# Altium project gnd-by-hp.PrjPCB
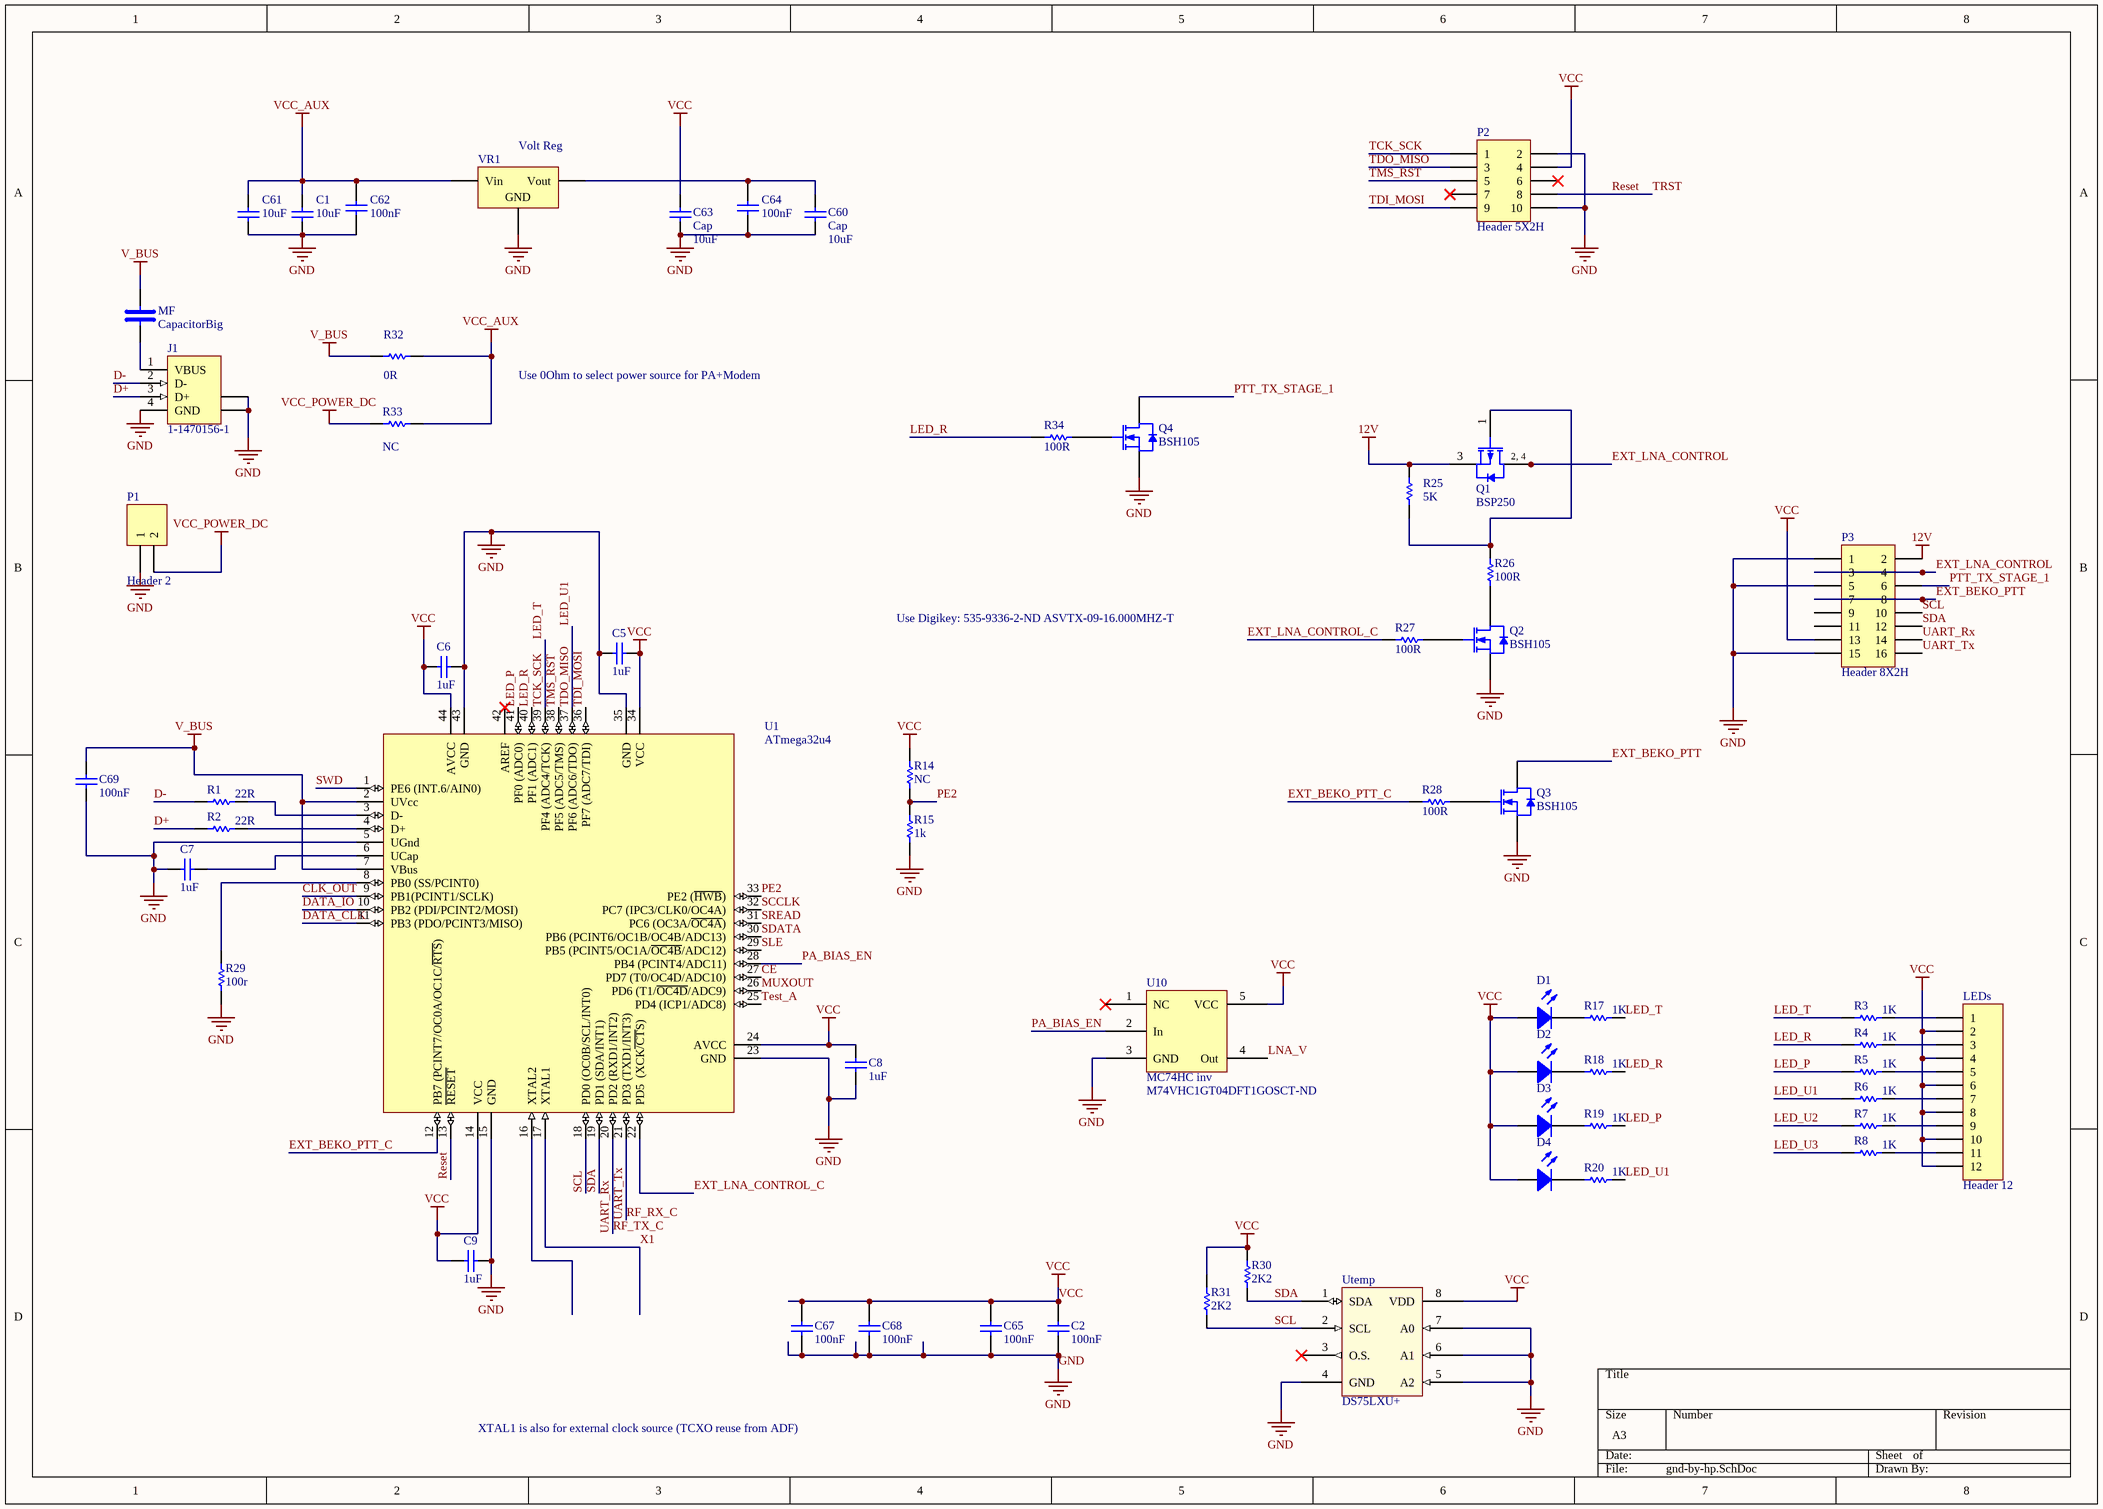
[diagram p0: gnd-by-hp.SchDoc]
4 sheets, 162 parts. Net scope: global (net labels, ports and power ports of the same name join across sheets).
Board files: gnd-by-hp.PcbDoc, aausat3_template.PCBDOC
Sheets:
  gnd-by-hp.SchDoc
  radio.SchDoc
  pa.SchDoc
  power.SchDoc

## Sheet gnd-by-hp.SchDoc
size A3; PageSetup: Record=PageOptions|CenterHorizontal=True|CenterVertical=True|PrintScale=0.71|XCorrection=1.00|YCorrection=1.00|PrintKind=0|BorderSize=5000000|LeftOffset=0|BottomOffset=0|Orientation=2|PaperLength=1000|PaperWidth=1000|Scale=100|PaperSource=7|PrintQuality=-4|MediaType=1|DitherType=10|PaperKind=A4|PrintScaleMode=1

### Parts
C1  value 10uF  [RAD-0.3]  (hidden comment: Cap)
C2  value 100nF  [C06]  (hidden comment: Capacitor)
C5  value 1uF  [CAPC3216L]  (hidden comment: Cap Semi)
C6  value 1uF  [CAPC3216L]  (hidden comment: Cap Semi)
C7  value 1uF  [CAPC3216L]  (hidden comment: Cap Semi)
C8  value 1uF  [CAPC3216L]  (hidden comment: Cap Semi)
C9  value 1uF  [CAPC3216L]  (hidden comment: Cap Semi)
C60  Cap  value 10uF  [RAD-0.3]
C61  value 10uF  [RAD-0.3]  (hidden comment: Cap)
C62  value 100nF  [C06]  (hidden comment: Capacitor)
C63  Cap  value 10uF  [RAD-0.3]
C64  value 100nF  [C06]  (hidden comment: Capacitor)
C65  value 100nF  [C06]  (hidden comment: Capacitor)
C67  value 100nF  [C06]  (hidden comment: Capacitor)
C68  value 100nF  [C06]  (hidden comment: Capacitor)
C69  value 100nF  [CAPC3216L]  (hidden comment: Cap Semi)
D1  LED  [L06]  (value not drawn)
D2  LED  [L06]  (value not drawn)
D3  LED  [L06]  (value not drawn)
D4  LED  [L06]  (value not drawn)
J1  1-1470156-1  [1-1470156]
LEDs  Header 12  [HDR1X12]
MF  CapacitorBig  [C1210]
P1  Header 2  [HDR1X2]
P2  Header 5X2H  [HDR2X5H]
P3  Header 8X2H  [HDR2X8H]
Q1  BSP250  [SOT223_N]
Q2  BSH105  [SOT23_N]
Q3  BSH105  [SOT23_N]
Q4  BSH105  [SOT23_N]
R1  value 22R  [AXIAL-0.5]  (hidden comment: Res Semi)
R2  value 22R  [AXIAL-0.5]  (hidden comment: Res Semi)
R3  value 1K  [AXIAL-0.5]  (hidden comment: Res Semi)
R4  value 1K  [AXIAL-0.5]  (hidden comment: Res Semi)
R5  value 1K  [AXIAL-0.5]  (hidden comment: Res Semi)
R6  value 1K  [AXIAL-0.5]  (hidden comment: Res Semi)
R7  value 1K  [AXIAL-0.5]  (hidden comment: Res Semi)
R8  value 1K  [AXIAL-0.5]  (hidden comment: Res Semi)
R14  value NC  [AXIAL-0.5]  (hidden comment: Res Semi)
R15  value 1k  [AXIAL-0.5]  (hidden comment: Res Semi)
R17  value 1K  [AXIAL-0.5]  (hidden comment: Res Semi)
R18  value 1K  [AXIAL-0.5]  (hidden comment: Res Semi)
R19  value 1K  [AXIAL-0.5]  (hidden comment: Res Semi)
R20  value 1K  [AXIAL-0.5]  (hidden comment: Res Semi)
R25  value 5K  [R06]  (hidden comment: Res Semi)
R26  value 100R  [R06]  (hidden comment: Res Semi)
R27  value 100R  [R06]  (hidden comment: Res Semi)
R28  value 100R  [R06]  (hidden comment: Res Semi)
R29  value 100r  [AXIAL-0.5]  (hidden comment: Res Semi)
R30  value 2K2  [AXIAL-0.5]  (hidden comment: Res Semi)
R31  value 2K2  [AXIAL-0.5]  (hidden comment: Res Semi)
R32  value 0R  [RESC1608L]  (hidden comment: Res Semi)
R33  value NC  [RESC1608L]  (hidden comment: Res Semi)
R34  value 100R  [R06]  (hidden comment: Res Semi)
U1  ATmega32u4  [44A_N]
U10  MC74HC inv  Supplier Part Number 1: M74VHC1GT04DFT1GOSCT-ND  [SOT353 for MC74HC]
Utemp  DS75LXU+  [uSOP8]
VR1  Volt Reg  [TO254P1510-3_4N]

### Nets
12V: P3.2 Q1.3(S) R25.2
GND: C1.1 C2.1 C5.1 C6.1 C7.2 C8.2 C9.1 C60.1 C61.1 C62.2 C63.1 C64.2 C65.1 C67.1 C68.1 C69.1 J1.4(GND) J1.5(SHLD) J1.6(SHLD) P1.1 P2.2 P2.10 P3.1 P3.5 P3.15 Q2.2(S) Q3.2(S) Q4.2(S) R15.1 R29.1 U1.5(UGnd) U1.15(GND) U1.23(GND) U1.35(GND) U1.43(GND) U10.3(GND) Utemp.4(GND) Utemp.5(A2) Utemp.6(A1) Utemp.7(A0) VR1.2(GND)
V_BUS: C69.2 MF.1 R32.1 U1.2(UVcc) U1.7(VBus)
VCC: C2.2 C5.2 C6.2 C8.1 C9.2 C63.2 C65.2 C67.2 C68.2 D1.1(A) D2.1(A) D3.1(A) D4.1(A) LEDs.2 LEDs.4 LEDs.6 LEDs.8 LEDs.10 LEDs.12 P2.4 P3.13 R14.2 R30.2 R31.2 U1.14(VCC) U1.24(AVCC) U1.34(VCC) U1.44(AVCC) U10.5(VCC) Utemp.8(VDD)
VCC_AUX: C1.2 C61.2 C62.1 R32.2 R33.2 VR1.1(Vin)
VCC_POWER_DC: P1.2 R33.1
CE: U1.27(PD7_(T0/OC4D/ADC10))
CLK_OUT: U1.9(PB1(PCINT1/SCLK))
D+: J1.3(D+) R2.1
D-: J1.2(D-) R1.1
DATA_CLK: U1.11(PB3_(PDO/PCINT3/MISO))
DATA_IO: U1.10(PB2_(PDI/PCINT2/MOSI))
EXT_BEKO_PTT: P3.7 P3.8 Q3.3(D)
EXT_BEKO_PTT_C: R28.2 U1.12(PB7_(PCINT7/OC0A/OC1C/~{RTS}))
EXT_LNA_CONTROL: P3.3 P3.4 Q1.2(D) Q1.4(D)
EXT_LNA_CONTROL_C: R27.2 U1.22(PD5__(XCK~{/CT}S))
LED_P: R5.1 R19.2 U1.41(PF0_(ADC0))
LED_R: R4.1 R18.2 R34.2 U1.40(PF1_(ADC1))
LED_T: P2.1 R3.1 R17.2 U1.39(PF4_(ADC4/TCK))  [also labelled TCK_SCK]
LED_U1: P2.3 R6.1 R20.2 U1.37(PF6_(ADC6/TDO))  [also labelled TDO_MISO]
LED_U2: R7.1
LED_U3: R8.1
LNA_V: U10.4(Out)
MUXOUT: U1.26(PD6_(T1/~{OC4D}/ADC9))
PA_BIAS_EN: U1.28(PB4_(PCINT4/ADC11)) U10.2(In)
PE2: R14.1 R15.2 U1.33(PE2_(~{HWB}))
PTT_TX_STAGE_1: P3.6 Q4.3(D)
Reset: P2.8 U1.13(~{RESET})  [also labelled TRST]
RF_RX_C: P3.16 U1.21(PD3_(TXD1/INT3))  [also labelled UART_Tx]
RF_TX_C: P3.14 U1.20(PD2_(RXD1/INT2))  [also labelled UART_Rx]
SCCLK: U1.32(PC7_(IPC3/CLK0/OC4A))
SCL: P3.10 R31.1 U1.18(PD0_(OC0B/SCL/INT0)) Utemp.2(SCL)
SDA: P3.12 R30.1 U1.19(PD1_(SDA/INT1)) Utemp.1(SDA)
SDATA: U1.30(PB6_(PCINT6/OC1B/OC4B/ADC13))
SLE: U1.29(PB5_(PCINT5/OC1A/~{OC4B}/ADC12))
SREAD: U1.31(PC6_(OC3A/~{OC4A}))
SWD: U1.1(PE6_(INT.6/AIN0))
TDI_MOSI: P2.9 U1.36(PF7_(ADC7/TDI))
Test_A: U1.25(PD4_(ICP1/ADC8))
TMS_RST: P2.5 U1.38(PF5_(ADC5/TMS))
X1: U1.17(XTAL1)
NetC7_1: C7.1 U1.6(UCap)
NetC60_2: C60.2 C64.1 VR1.3(Vout)
NetD1_2: D1.2(K) R17.1
NetD2_2: D2.2(K) R18.1
NetD3_2: D3.2(K) R19.1
NetD4_2: D4.2(K) R20.1
NetJ1_1: J1.1(VBUS) MF.2
NetLEDs_1: LEDs.1 R3.2
NetLEDs_3: LEDs.3 R4.2
NetLEDs_5: LEDs.5 R5.2
NetLEDs_7: LEDs.7 R6.2
NetLEDs_9: LEDs.9 R7.2
NetLEDs_11: LEDs.11 R8.2
NetQ1_1: Q1.1(G) R25.1 R26.1
NetQ2_1: Q2.1(G) R27.1
NetQ2_3: Q2.3(D) R26.2
NetQ3_1: Q3.1(G) R28.1
NetQ4_1: Q4.1(G) R34.1
NetR1_2: R1.2 U1.3(D-)
NetR2_2: R2.2 U1.4(D+)
NetR29_2: R29.2 U1.8(PB0_(SS/PCINT0))

Not connected (* = marked no-connect by the designer): P2 6* 7*; P3 9 11; U1 16(XTAL2) 42(AREF)*; U10 1(NC)*; Utemp 3(O.S.)*

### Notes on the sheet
- Use 0Ohm to select power source for PA+Modem
- Use Digikey: 535-9336-2-ND ASVTX-09-16.000MHZ-T
- XTAL1 is also for external clock source (TCXO reuse from ADF)

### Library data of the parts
C1 C60 C61 C63 = Cap: Capacitor
C2 C62 C64 C65 C67 C68 = Capacitor: Capacitor, standard
C5-C9 C69 = Cap Semi: Capacitor (Semiconductor SIM Model)
D1-D4 = LED: Typical RED GaAs LED
J1 = 1-1470156-1: USB 1.1, Right Angle, Thru-Hole, B Type, Receptacle, 4 Position, White; ContactMaterial: Phosphor Bronze; ContactPlating: Gold over Nickel; TerminationLength: 3.00mm [0.118in.]; PCB_Layout: Complies with manufacturer's recommendation.; DrillSize: Corresponds to nominal value.; PanelGround: Without
LEDs = Header 12: Header, 12-Pin
MF = CapacitorBig: Capacitor for PRU etc.; By: Troels Jessen; Username: tjessen
P1 = Header 2: Header, 2-Pin
P2 = Header 5X2H: Header, 5-Pin, Dual row, Right Angle
P3 = Header 8X2H: Header, 8-Pin, Dual row, Right Angle
Q1 = BSP250: P-channel Enhancement Mode Vertical D-MOSFET
Q2-Q4 = BSH105: N-channel Enhancement Mode MOSFET
R1-R8 R14 R15 R17-R20 R25-R34 = Res Semi: Semiconductor Resistor
U1 = ATmega32u4: 8-Bit AVR Microcontroller with 32K Bytes of In-System Programmable Flash Memory
Utemp = DS75LXU+: Digital Thermometer and Thermostat; By: hp000
VR1 = Volt Reg: Voltage Regulator

## Sheet radio.SchDoc
size A3
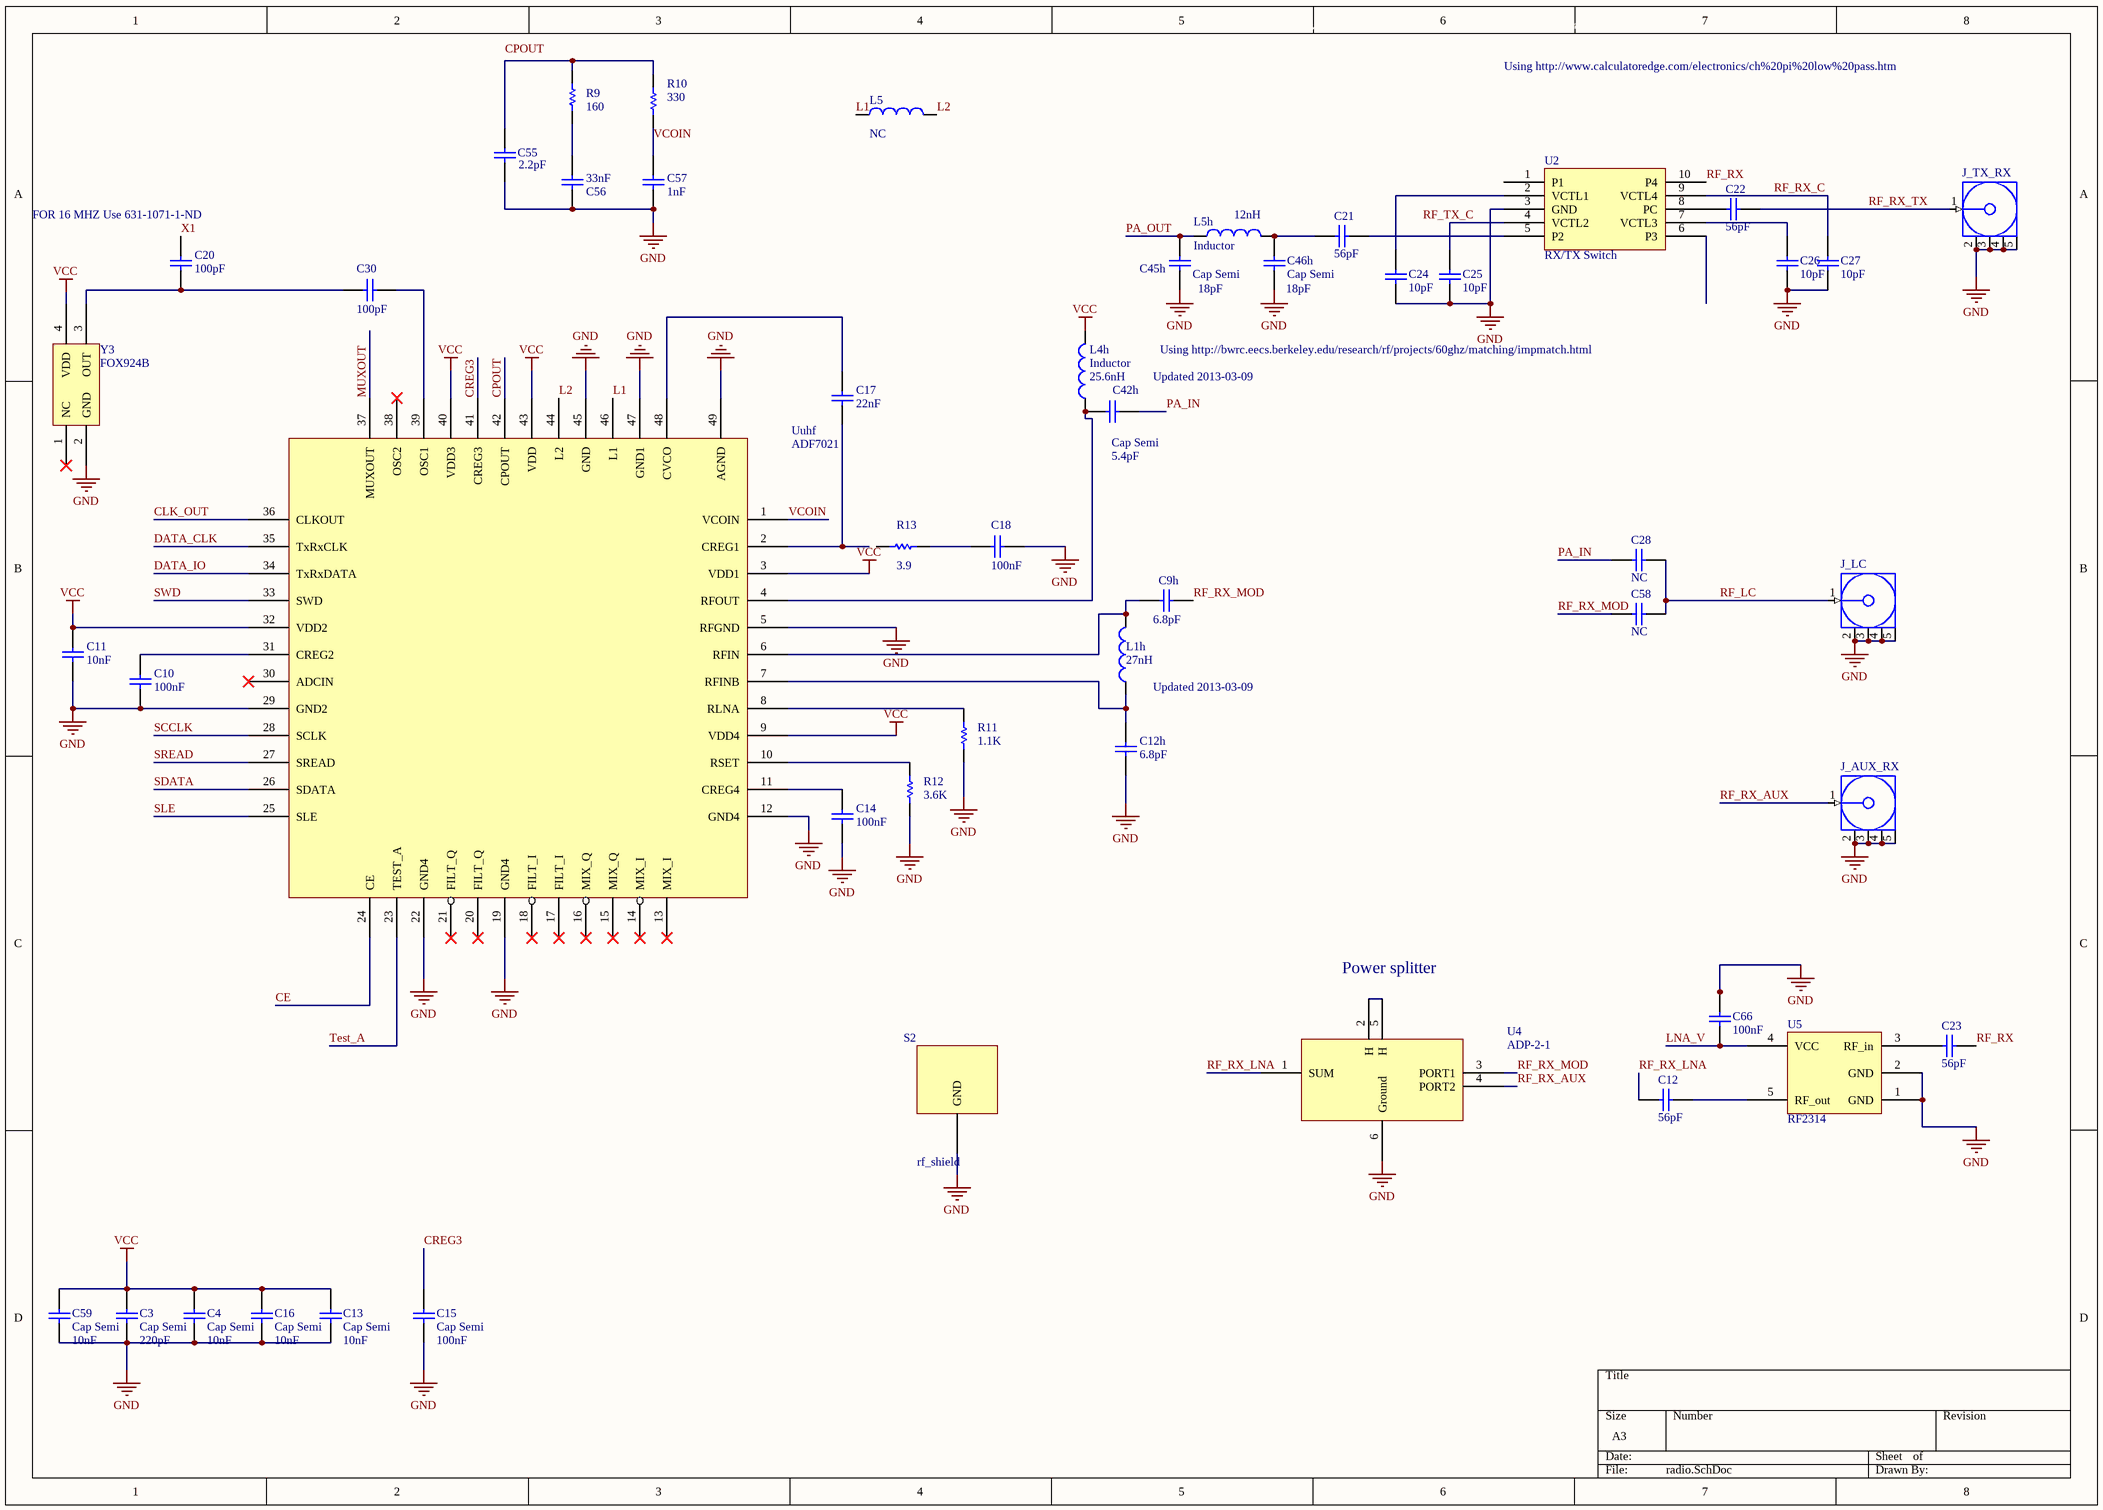
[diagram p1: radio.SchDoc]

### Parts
C3  Cap Semi  value 220pF  [C06]
C4  Cap Semi  value 10nF  [C06]
C9h  value 6.8pF  [C06]  (hidden comment: Cap Semi)
C10  value 100nF  [C06]  (hidden comment: Cap Semi)
C11  value 10nF  [C06]  (hidden comment: Cap Semi)
C12  value 56pF  [C06]  (hidden comment: Capacitor)
C12h  value 6.8pF  [C06]  (hidden comment: Cap Semi)
C13  Cap Semi  value 10nF  [C06]
C14  value 100nF  [C06]  (hidden comment: Cap Semi)
C15  Cap Semi  value 100nF  [C06]
C16  Cap Semi  value 10nF  [C06]
C17  value 22nF  [C06]  (hidden comment: Cap Semi)
C18  value 100nF  [C06]  (hidden comment: Cap Semi)
C20  value 100pF  [C06]  (hidden comment: Cap Semi)
C21  value 56pF  [C06]  (hidden comment: Capacitor)
C22  value 56pF  [C06]  (hidden comment: Capacitor)
C23  value 56pF  [C06]  (hidden comment: Capacitor)
C24  value 10pF  [C06]  (hidden comment: Capacitor)
C25  value 10pF  [C06]  (hidden comment: Capacitor)
C26  value 10pF  [C06]  (hidden comment: Capacitor)
C27  value 10pF  [C06]  (hidden comment: Capacitor)
C28  value NC  [C06]  (hidden comment: Capacitor)
C30  value 100pF  [C06]  (hidden comment: Cap Semi)
C42h  Cap Semi  value 5.4pF  [C06]
C45h  Cap Semi  value 18pF  [C06]
C46h  Cap Semi  value 18pF  [C06]
C55  value 2.2pF  [C06]  (hidden comment: Cap Semi)
C56  value 33nF  [C06]  (hidden comment: Cap Semi)
C57  value 1nF  [C06]  (hidden comment: Cap Semi)
C58  value NC  [C06]  (hidden comment: Capacitor)
C59  Cap Semi  value 10nF  [C06]
C66  value 100nF  [C06]  (hidden comment: Capacitor)
J_AUX_RX  COAX-F  [MCX5.08-H5]  (value not drawn)
J_LC  COAX-F  [MCX5.08-H5]  (value not drawn)
J_TX_RX  COAX-F  [MCX5.08-H5]  (value not drawn)
L1h  value 27nH  [B82464-G4]  (hidden comment: Inductor)
L4h  Inductor  value 25.6nH  [B82464-G4]
L5  value NC  [INDC1005AL]  (hidden comment: Inductor)
L5h  Inductor  value 12nH  [B82464-G4]
R9  value 160  [R06]  (hidden comment: Res Semi)
R10  value 330  [R06]  (hidden comment: Res Semi)
R11  value 1.1K  [R06]  (hidden comment: Res Semi)
R12  value 3.6K  [R06]  (hidden comment: Res Semi)
R13  value 3.9  [R06]  (hidden comment: Res Semi)
S2  rf_shield  [rf_can_shield]
U2  RX/TX Switch  [FLP10]
U4  ADP-2-1  [ADP-2-1]
U5  RF2314  [SOT95P280X144-5M]
Uuhf  ADF7021  [QFN50P700X700X100-48M]
Y3  FOX924B  [Fox924]

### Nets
GND: C3.1 C4.1 C10.1 C11.1 C12h.1 C13.1 C14.1 C15.1 C16.1 C18.2 C24.1 C25.1 C26.1 C27.1 C45h.1 C46h.1 C55.1 C56.1 C57.1 C59.1 C66.1 J_AUX_RX.2(GND) J_AUX_RX.3(GND) J_AUX_RX.4(GND) J_AUX_RX.5(GND) J_LC.2(GND) J_LC.3(GND) J_LC.4(GND) J_LC.5(GND) J_TX_RX.2(GND) J_TX_RX.3(GND) J_TX_RX.4(GND) J_TX_RX.5(GND) R11.2 R12.1 S2.0(GND) U2.3(GND) U4.6(Ground) U5.1(GND) U5.2(GND) Uuhf.5(RFGND) Uuhf.12(GND4) Uuhf.19(GND4) Uuhf.22(GND4) Uuhf.29(GND2) Uuhf.45(GND) Uuhf.47(GND1) Uuhf.49(AGND) Y3.2(GND)
VCC: C3.2 C4.2 C11.2 C13.2 C16.2 C59.2 L4h.2 Uuhf.3(VDD1) Uuhf.9(VDD4) Uuhf.32(VDD2) Uuhf.40(VDD3) Uuhf.43(VDD) Y3.4(VDD)
CE: Uuhf.24(CE)
CLK_OUT: Uuhf.36(CLKOUT)
CPOUT: Uuhf.42(CPOUT)
CREG3: C15.2 Uuhf.41(CREG3)
DATA_CLK: Uuhf.35(TxRxCLK)
DATA_IO: Uuhf.34(TxRxDATA)
L1: L5.1 Uuhf.46(L1)
L2: L5.2 Uuhf.44(L2)
LNA_V: C66.2 U5.4(VCC)
MUXOUT: Uuhf.37(MUXOUT)
PA_IN: C28.2 C42h.2
PA_OUT: C45h.2 L5h.1
RF_LC: C28.1 C58.1 J_LC.1(Signal)
RF_RX: C23.1 U2.10(P4)
RF_RX_AUX: J_AUX_RX.1(Signal) U4.4(PORT2)
RF_RX_C: C27.2 U2.9(VCTL4)
RF_RX_LNA: C12.2 U4.1(SUM)
RF_RX_MOD: C9h.1 C58.2 U4.3(PORT1)
RF_RX_TX: C22.1 J_TX_RX.1(Signal)
SCCLK: Uuhf.28(SCLK)
SDATA: Uuhf.26(SDATA)
SLE: Uuhf.25(SLE)
SREAD: Uuhf.27(SREAD)
SWD: Uuhf.33(SWD)
Test_A: Uuhf.23(TEST_A)
VCOIN: C57.2 R10.1 Uuhf.1(VCOIN)
X1: C20.2
NetC9h_2: C9h.2 L1h.2 Uuhf.6(RFIN)
NetC10_2: C10.2 Uuhf.31(CREG2)
NetC12_1: C12.1 U5.5(RF_out)
NetC12h_2: C12h.2 L1h.1 Uuhf.7(RFINB)
NetC14_2: C14.2 Uuhf.11(CREG4)
NetC17_1: C17.1 Uuhf.2(CREG1)
NetC17_2: C17.2 Uuhf.48(CVCO)
NetC18_1: C18.1 R13.2
NetC20_1: C20.1 C30.1 Y3.3(OUT)
NetC21_1: C21.1 U2.5(P2)
NetC21_2: C21.2 C46h.2 L5h.2
NetC22_2: C22.2 U2.8(PC)
NetC23_2: C23.2 U5.3(RF_in)
NetC24_2: C24.2 U2.2(VCTL1)
NetC25_2: C25.2 U2.4(VCTL2)
NetC26_2: C26.2 U2.7(VCTL3)
NetC30_2: C30.2 Uuhf.39(OSC1)
NetC42h_1: C42h.1 L4h.1 Uuhf.4(RFOUT)
NetC55_2: C55.2 R9.2 R10.2
NetC56_2: C56.2 R9.1
NetR11_1: R11.1 Uuhf.8(RLNA)
NetR12_2: R12.2 Uuhf.10(RSET)
NetU4_2: U4.2(H) U4.5(H)

Not connected (* = marked no-connect by the designer): R13 1; U2 1(P1) 6(P3); Uuhf 13(MIX_I)* 14(MIX_I)* 15(MIX_Q)* 16(MIX_Q)* 17(FILT_I)* 18(FILT_I)* 20(FILT_Q)* 21(FILT_Q)* 30(ADCIN)* 38(OSC2)*; Y3 1(NC)*

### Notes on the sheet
- Using http://www.calculatoredge.com/electronics/ch%20pi%20low%20pass.htm
- (near C20) FOR 16 MHZ Use 631-1071-1-ND
- Updated 2013-03-09
- Using http://bwrc.eecs.berkeley.edu/research/rf/projects/60ghz/matching/impmatch.html
- (near L1h) Updated 2013-03-09
- Power splitter
- Labels drawn without touching a wire or pin: CPOUT, RF_TX_C

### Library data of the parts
C3 C4 C9h C10 C11 C12h C13-C18 C20 C30 C42h C45h C46h C55-C57 C59 = Cap Semi: Capacitor (Semiconductor SIM Model)
C12 C21-C28 C58 C66 = Capacitor: Capacitor, standard
J_AUX_RX J_LC J_TX_RX = COAX-F: RF Coaxial PCB Connector, MCX; Thru-Hole, Right-Angle Mount Socket, Blunt Post Terminal, 50 Ohm Impedance; PCB_Layout: Complies with manufacturer's recommendation.; DrillSize: Corresponds to nominal value.
L5 = Inductor: Code_IEC: 1005
R9-R13 = Res Semi: Semiconductor Resistor
S2 = rf_shield: RF Shielding; Manufacturer: Fotofab; By: HP; Description: SHIELD RF STD 1 X 1 X .25"
U2 = NJG1519KC1-TE3: SP4T SWITCH GaAs MMIC, up to 2.5GHz.; By: Hans Peter Mortensen
U4 = ADP-2-1: 2 way power splitter; By: Hans Peter aau; Producent: Mini-Circuits
U5 = RF2314: LNA from RFMD no external components; By: Nikolaj B. Pedersen
Uuhf = ADF7021: ADF7021 transceiver; By: Nikolaj Bisgaard Pedersen
Y3 = FOX924B: FOX924B TCXO 19.44 MHz; By: Nikolaj B. Pedersen; Username: Markem

## Sheet pa.SchDoc
size A4
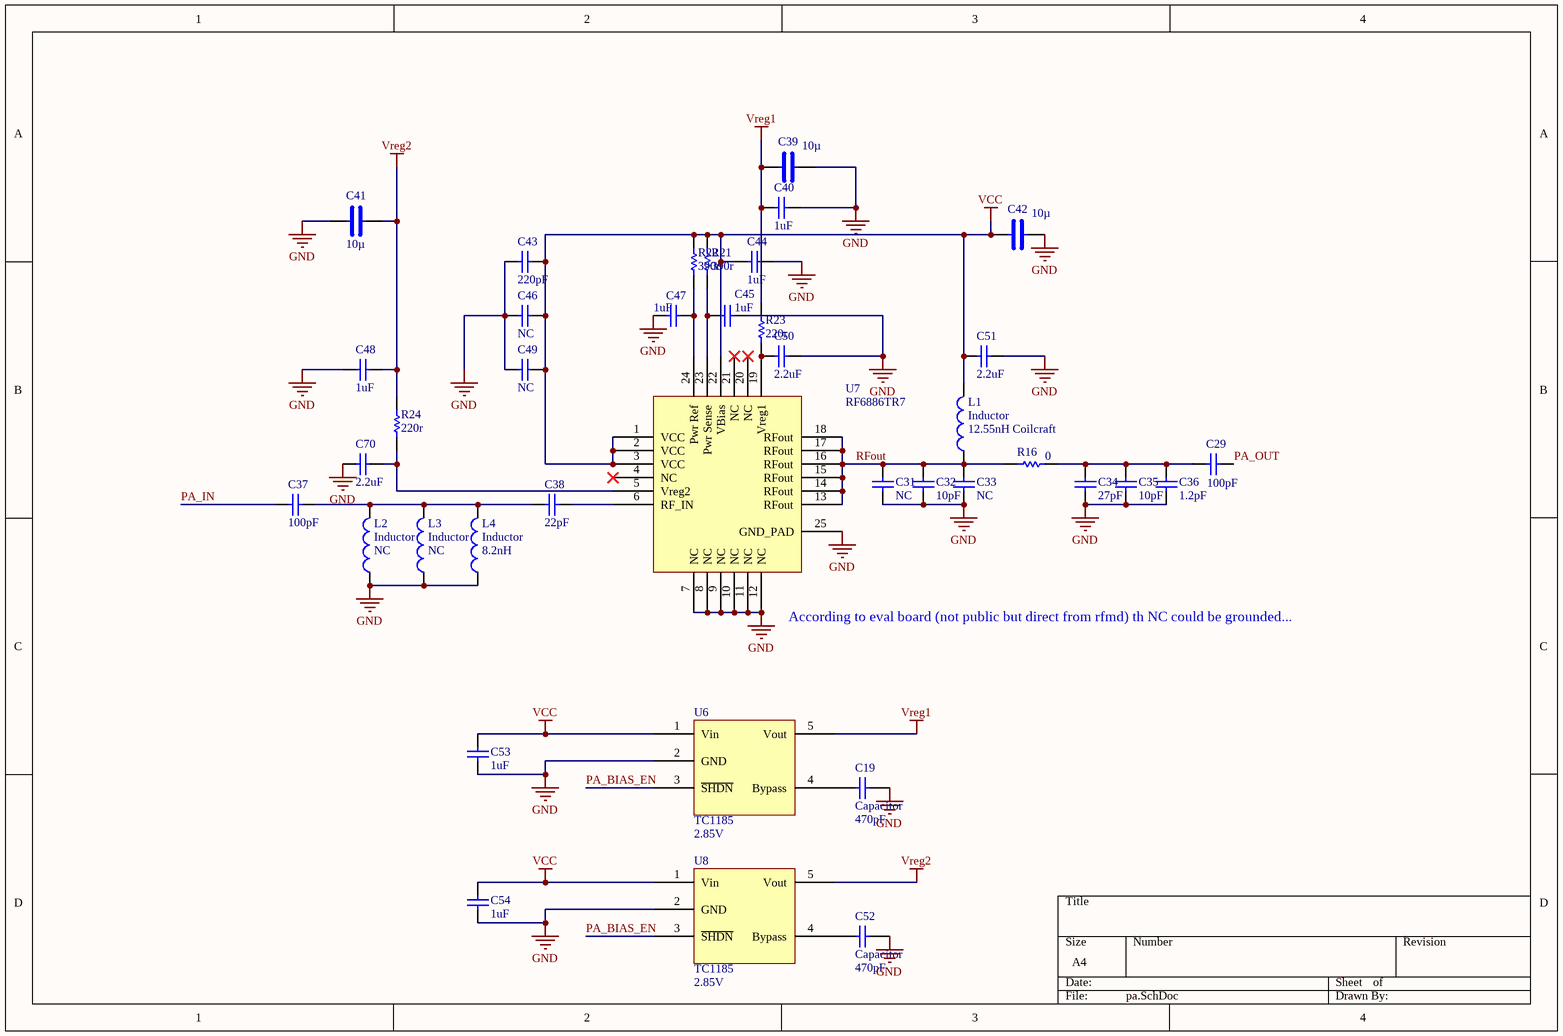
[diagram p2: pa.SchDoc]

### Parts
C19  Capacitor  value 470pF  [C06]
C29  value 100pF  [CAPC3216L]  (hidden comment: Cap Semi)
C31  value NC  [CAPC3216L]  (hidden comment: Cap Semi)
C32  value 10pF  [CAPC3216L]  (hidden comment: Cap Semi)
C33  value NC  [CAPC3216L]  (hidden comment: Cap Semi)
C34  value 27pF  [CAPC3216L]  (hidden comment: Cap Semi)
C35  value 10pF  [CAPC3216L]  (hidden comment: Cap Semi)
C36  value 1.2pF  [CAPC3216L]  (hidden comment: Cap Semi)
C37  value 100pF  [CAPC3216L]  (hidden comment: Cap Semi)
C38  value 22pF  [CAPC3216L]  (hidden comment: Cap Semi)
C39  value 10µ  [C1210]  (hidden comment: CapacitorBig)
C40  value 1uF  [CAPC3216L]  (hidden comment: Cap Semi)
C41  value 10µ  [C1210]  (hidden comment: CapacitorBig)
C42  value 10µ  [C1210]  (hidden comment: CapacitorBig)
C43  value 220pF  [CAPC3216L]  (hidden comment: Cap Semi)
C44  value 1uF  [CAPC3216L]  (hidden comment: Cap Semi)
C45  value 1uF  [CAPC3216L]  (hidden comment: Cap Semi)
C46  value NC  [CAPC3216L]  (hidden comment: Cap Semi)
C47  value 1uF  [CAPC3216L]  (hidden comment: Cap Semi)
C48  value 1uF  [CAPC3216L]  (hidden comment: Cap Semi)
C49  value NC  [CAPC3216L]  (hidden comment: Cap Semi)
C50  value 2.2uF  [CAPC3216L]  (hidden comment: Cap Semi)
C51  value 2.2uF  [CAPC3216L]  (hidden comment: Cap Semi)
C52  Capacitor  value 470pF  [C06]
C53  value 1uF  [CAPC3216L]  (hidden comment: Cap Semi)
C54  value 1uF  [CAPC3216L]  (hidden comment: Cap Semi)
C70  value 2.2uF  [CAPC3216L]  (hidden comment: Cap Semi)
L1  Inductor  value 12.55nH Coilcraft  [INDC1005AL]
L2  Inductor  value NC  [INDC1005AL]
L3  Inductor  value NC  [INDC1005AL]
L4  Inductor  value 8.2nH  [INDC1005AL]
R16  value 0  [AXIAL-0.5]  (hidden comment: Res Semi)
R21  value 390r  [AXIAL-0.5]  (hidden comment: Res Semi)
R22  value 390r  [AXIAL-0.5]  (hidden comment: Res Semi)
R23  value 220r  [AXIAL-0.5]  (hidden comment: Res Semi)
R24  value 220r  [AXIAL-0.5]  (hidden comment: Res Semi)
U6  TC1185  Voltage: 2.85V  [SOT23 - 5 for microchip]
U7  RF6886TR7  [QFN24-4-4]
U8  TC1185  Voltage: 2.85V  [SOT23 - 5 for microchip]

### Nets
GND: C19.1 C31.1 C32.1 C33.1 C34.1 C35.1 C36.1 C39.2 C40.1 C41.1 C42.2 C43.2 C44.2 C45.2 C46.2 C47.1 C48.2 C49.2 C50.1 C51.1 C52.1 C53.1 C54.1 C70.2 L2.1 L3.1 L4.1 U6.2(GND) U7.7(NC) U7.8(NC) U7.9(NC) U7.10(NC) U7.11(NC) U7.12(NC) U7.25(GND_PAD) U8.2(GND)
VCC: C42.1 C43.1 C44.1 C46.1 C49.1 C51.2 C53.2 C54.2 L1.2 R21.2 R22.2 U6.1(Vin) U7.1(VCC) U7.2(VCC) U7.3(VCC) U7.22(VBias) U8.1(Vin)
Vreg1: C39.1 C40.2 R23.1 U6.5(Vout)
Vreg2: C41.2 C48.1 R24.2 U8.5(Vout)
PA_BIAS_EN: U6.3(~{SHDN}) U8.3(~{SHDN})
PA_IN: C37.2
PA_OUT: C29.2
RFout: C31.2 C32.2 C33.2 L1.1 R16.1 U7.13(RFout) U7.14(RFout) U7.15(RFout) U7.16(RFout) U7.17(RFout) U7.18(RFout)
NetC19_2: C19.2 U6.4(Bypass)
NetC29_1: C29.1 C34.2 C35.2 C36.2 R16.2
NetC37_1: C37.1 C38.2 L2.2 L3.2 L4.2
NetC38_1: C38.1 U7.6(RF_IN)
NetC45_1: C45.1 R21.1 U7.23(Pwr_Sense)
NetC47_2: C47.2 R22.1 U7.24(Pwr_Ref)
NetC50_2: C50.2 R23.2 U7.19(Vreg1)
NetC52_2: C52.2 U8.4(Bypass)
NetC70_1: C70.1 R24.1 U7.5(Vreg2)

Not connected (* = marked no-connect by the designer): U7 4(NC)* 20(NC)* 21(NC)*

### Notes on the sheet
- (near U7) According to eval board (not public but direct from rfmd) th NC could be grounded...

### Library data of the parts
C19 C52 = Capacitor: Capacitor, standard
C29 C31-C38 C40 C43-C51 C53 C54 C70 = Cap Semi: Capacitor (Semiconductor SIM Model)
C39 C41 C42 = CapacitorBig: as MF on sheet gnd-by-hp
L1-L4 = Inductor: Code_IEC: 1005
R16 R21-R24 = Res Semi: Semiconductor Resistor
U6 U8 = TC1185: Voltage regulater from Microchip; By: Nikolaj B. Pedersen

## Sheet power.SchDoc
size A4
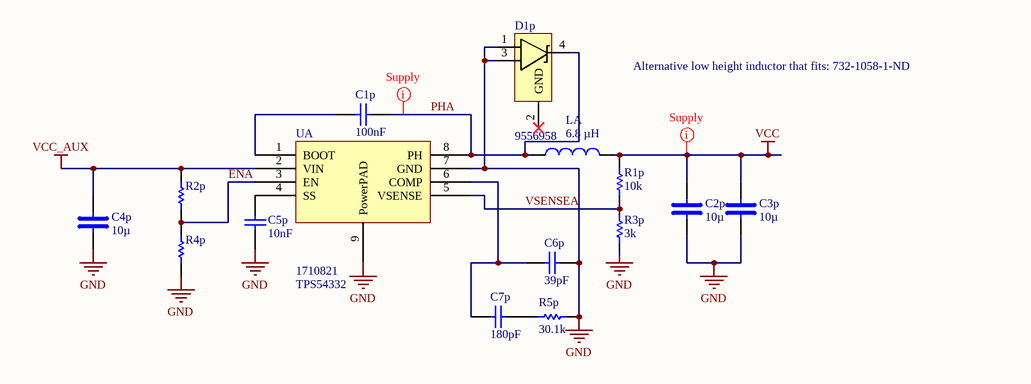
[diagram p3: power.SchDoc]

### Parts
C1p  value 100nF  [C06]  (hidden comment: Capacitor)
C2p  value 10µ  [C1210]  (hidden comment: CapacitorBig)
C3p  value 10µ  [C1210]  (hidden comment: CapacitorBig)
C4p  value 10µ  [C1210]  (hidden comment: CapacitorBig)
C5p  value 10nF  [C06]  (hidden comment: Capacitor)
C6p  value 39pF  [C06]  (hidden comment: Capacitor)
C7p  value 180pF  [C06]  (hidden comment: Capacitor)
D1p  Supplier Part Number 1: 9556958  [TO228P1003X238-3N]  (hidden comment: MBRD360)
LA  value 6.8 µH  [B82464-G4]  (hidden comment: Inductor)
R1p  value 10k  [R06]  (hidden comment: Resistor)
R2p  Resistor  [R06]  (value not drawn)
R3p  value 3k  [R06]  (hidden comment: Resistor)
R4p  Resistor  [R06]  (value not drawn)
R5p  value 30.1k  [R06]  (hidden comment: Resistor)
UA  Supplier Part Number 1: 1710821  [8SO_PowerPAD]  (hidden comment: TPS54332DDA)

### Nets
GND: C2p.1 C3p.1 C4p.1 C5p.1 C6p.2 D1p.1 D1p.3 R3p.1 R4p.1 R5p.2 UA.7(GND) UA.9(PowerPAD)
VCC: C2p.2 C3p.2 LA.2 R1p.2
VCC_AUX: C4p.2 R2p.2 UA.2(VIN)
ENA: R2p.1 R4p.2 UA.3(EN)
PHA: C1p.2 D1p.4 LA.1 UA.8(PH)
VSENSEA: R1p.1 R3p.2 UA.5(VSENSE)
NetC1p_1: C1p.1 UA.1(BOOT)
NetC5p_2: C5p.2 UA.4(SS)
NetC6p_1: C6p.1 C7p.1 UA.6(COMP)
NetC7p_2: C7p.2 R5p.1

Not connected (* = marked no-connect by the designer): D1p 2(GND)*

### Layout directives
net class Supply: PHA, VCC

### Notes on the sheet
- Alternative low height inductor that fits: 732-1058-1-ND

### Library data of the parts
C1p C5p C6p C7p = Capacitor: Capacitor, standard
C2p C3p C4p = CapacitorBig: as MF on sheet gnd-by-hp
D1p = MBRD360: High-Current Surface Mount Schottky Rectifier 3A; By: HP
R1p R2p R3p R4p R5p = Resistor: By: Troels Jessen; Username: tjessen
UA = TPS54332: 3.5A, 28V, 1MHz, STEP DOWN SWIFT DC/DC CONVERTER WITH Eco-mode™; By: HP

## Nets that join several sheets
GND: gnd-by-hp (41 pins), radio (49 pins), pa (36 pins), power (12 pins)
VCC: gnd-by-hp (30 pins), radio (13 pins), pa (17 pins), power (C2p.2 C3p.2 LA.2 R1p.2)
VCC_AUX: gnd-by-hp (6 pins), power (C4p.2 R2p.2 UA.2)
CE: gnd-by-hp (U1.27), radio (Uuhf.24)
CLK_OUT: gnd-by-hp (U1.9), radio (Uuhf.36)
DATA_CLK: gnd-by-hp (U1.11), radio (Uuhf.35)
DATA_IO: gnd-by-hp (U1.10), radio (Uuhf.34)
LNA_V: gnd-by-hp (U10.4), radio (C66.2 U5.4)
MUXOUT: gnd-by-hp (U1.26), radio (Uuhf.37)
PA_BIAS_EN: gnd-by-hp (U1.28 U10.2), pa (U6.3 U8.3)
PA_IN: radio (C28.2 C42h.2), pa (C37.2)
PA_OUT: radio (C45h.2 L5h.1), pa (C29.2)
RF_RX_C: gnd-by-hp (P3.16 U1.21), radio (C27.2 U2.9)
SCCLK: gnd-by-hp (U1.32), radio (Uuhf.28)
SDATA: gnd-by-hp (U1.30), radio (Uuhf.26)
SLE: gnd-by-hp (U1.29), radio (Uuhf.25)
SREAD: gnd-by-hp (U1.31), radio (Uuhf.27)
SWD: gnd-by-hp (U1.1), radio (Uuhf.33)
Test_A: gnd-by-hp (U1.25), radio (Uuhf.23)
X1: gnd-by-hp (U1.17), radio (C20.2)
